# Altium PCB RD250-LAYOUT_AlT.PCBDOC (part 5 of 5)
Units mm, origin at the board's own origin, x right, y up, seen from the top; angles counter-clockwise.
Board outline 318.5 x 135 mm, 6 copper layers (TOP, Mid-Layer 1, Mid-Layer 2, Mid-Layer 3, Mid-Layer 4, BOTTOM), stack 1.422 mm thick; 550 components, 251 nets, 1350 pads, 626 vias.
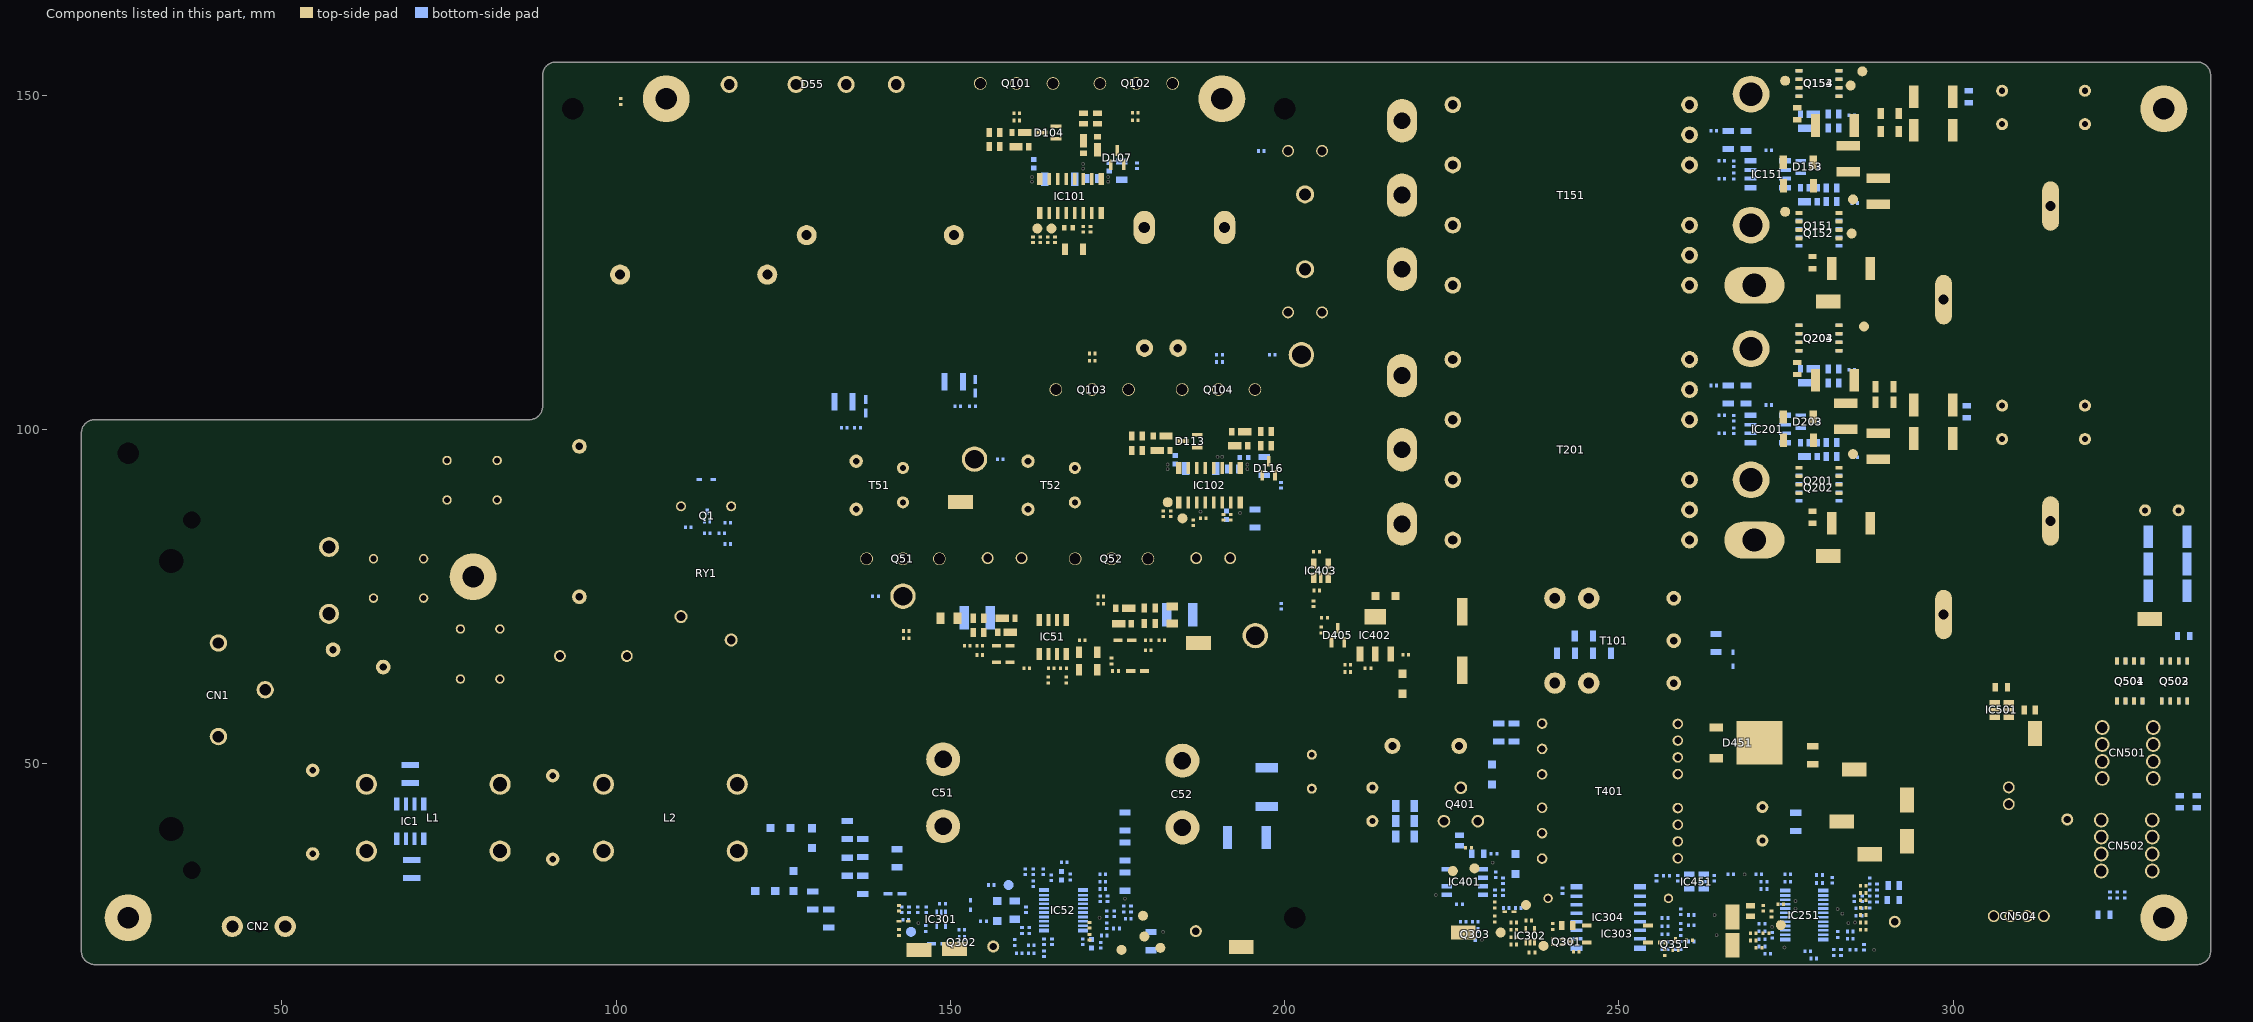
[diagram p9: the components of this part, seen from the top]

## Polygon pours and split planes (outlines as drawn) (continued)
PN on BOTTOM "BOTTOM323" (solid, pour order 144): 138.518,79.35 cw(c138.518,79.5) 138.419,79.612 138.448,79.639 cw(c138.55,79.529) 138.7,79.529 138.7,79.5 cw(c138.55,79.5) 138.55,79.35
PN on BOTTOM "BOTTOM322" (solid, pour order 143): 136.35,79.35 cw(c136.35,79.5) 136.2,79.5 136.2,79.548 cw(c136.35,79.548) 136.454,79.656 ccw(c137.46,80.7) 136.501,79.612 cw(c136.402,79.5) 136.402,79.35
LGND on BOTTOM "BOTTOM321" (solid, pour order 142): 76 vertices, not listed, extent 282.35,127.25 325.6,154.5
no net on BOTTOM "BOTTOM320" (solid, pour order 141): 17 vertices, not listed, extent 327.36,144.35 335.55,152.047
CONN003 on BOTTOM "BOTTOM319" (solid, pour order 140): 74 vertices, not listed, extent 189.15,104.9 219.95,149.4
LGND on BOTTOM "BOTTOM318" (solid, pour order 139): 48 vertices, not listed, extent 258.02,26.328 309.422,41.735
SIG00852 on BOTTOM "BOTTOM317" (solid, pour order 138): 270.7,42.25 cw(c270.7,42.4) 270.55,42.4 270.55,43.988 cw(c270.7,43.988) 270.594,44.094 270.906,44.406 cw(c271.012,44.3) 271.012,44.45 276.538,44.45 cw(c276.538,44.3) 276.644,44.406 277.306,43.744 cw(c277.2,43.638) 277.35,43.638 277.35,42.4 cw(c277.2,42.4) 277.2,42.25
SIG00343 on BOTTOM "BOTTOM316" (solid, pour order 137): 70 vertices, not listed, extent 153.65,73.05 242.16,153.1
SIG00332 on BOTTOM "BOTTOM315" (solid, pour order 136): 22 vertices, not listed, extent 257.705,61.614 268.45,67.4
CS on BOTTOM "BOTTOM314" (solid, pour order 135): 265.85,62 cw(c265.85,62.15) 265.7,62.15 265.7,65.2 cw(c265.85,65.2) 265.85,65.35 268.3,65.35 cw(c268.3,65.2) 268.45,65.2 268.45,62.15 cw(c268.3,62.15) 268.3,62
VCC12R0_2 on BOTTOM "BOTTOM313" (solid, pour order 134): 33 vertices, not listed, extent 278.25,26.376 314.522,49.25
PN on BOTTOM "BOTTOM312" (solid, pour order 133): 183.562,37.25 cw(c183.562,37.4) 183.456,37.294 181.944,38.806 cw(c182.05,38.912) 181.9,38.912 181.9,42.238 cw(c182.05,42.238) 181.944,42.344 183.606,44.006 cw(c183.712,43.9) 183.712,44.05 189.688,44.05 cw(c189.688,43.9) 189.794,44.006 192.156,41.644 cw(c192.05,41.538) 192.2,41.538 192.2,37.4 cw(c192.05,37.4) 192.05,37.25
SIG00343 on BOTTOM "BOTTOM311" (solid, pour order 132): 29 vertices, not listed, extent 177.741,111.596 201.4,118.55
PN on BOTTOM "BOTTOM310" (solid, pour order 131): 74 vertices, not listed, extent 182.7,106.072 197.949,113.7
CONN002 on BOTTOM "BOTTOM309" (solid, pour order 130): 183.4,95.75 cw(c183.4,95.9) 183.25,95.9 183.25,96.35 cw(c183.4,96.35) 183.4,96.5 187,96.5 cw(c187,96.35) 187.15,96.35 187.15,96.112 cw(c187,96.112) 187.106,96.006 186.969,95.869 cw(c186.863,95.975) 186.863,95.825 185.225,95.825 185.194,95.794 cw(c185.088,95.9) 185.088,95.75
SIG00345 on BOTTOM "BOTTOM308" (solid, pour order 129): 182.912,93.2 cw(c182.912,93.35) 182.806,93.244 182.244,93.806 cw(c182.35,93.912) 182.2,93.912 182.2,94.888 cw(c182.35,94.888) 182.244,94.994 182.431,95.181 cw(c182.537,95.075) 182.537,95.225 185.65,95.225 cw(c185.65,95.075) 185.8,95.075 185.8,93.35 cw(c185.65,93.35) 185.65,93.2
SIG00334 on BOTTOM "BOTTOM307" (solid, pour order 128): 162.162,136.3 cw(c162.162,136.45) 162.055,136.345 161.844,136.556 cw(c161.95,136.662) 161.8,136.662 161.8,139.238 cw(c161.95,139.238) 161.844,139.344 161.845,139.345 162.006,139.506 cw(c162.112,139.4) 162.112,139.55 163.138,139.55 cw(c163.138,139.4) 163.244,139.506 164.406,138.344 cw(c164.3,138.238) 164.45,138.238 164.45,136.45 cw(c164.3,136.45) 164.3,136.3
SIG00362 on BOTTOM "BOTTOM306" (solid, pour order 127): 164.762,139.75 cw(c164.762,139.9) 164.656,139.794 164.4,140.05 162.2,140.05 cw(c162.2,140.2) 162.05,140.2 162.05,141 cw(c162.2,141) 162.2,141.15 166.2,141.15 cw(c166.2,141) 166.35,141 166.35,140.212 cw(c166.2,140.212) 166.306,140.106 165.994,139.794 cw(c165.888,139.9) 165.888,139.75
SIG00354 on BOTTOM "BOTTOM305" (solid, pour order 126): 189.3,93.2 cw(c189.3,93.35) 189.15,93.35 189.15,94.9 cw(c189.3,94.9) 189.3,95.05 191.638,95.05 cw(c191.638,94.9) 191.744,95.006 191.906,94.844 cw(c191.8,94.738) 191.95,94.738 191.95,93.512 cw(c191.8,93.512) 191.906,93.406 191.744,93.244 cw(c191.638,93.35) 191.638,93.2
SIG00353 on BOTTOM "BOTTOM304" (solid, pour order 125): 39 vertices, not listed, extent 189.65,92.74 197.408,96.25
SIG00353 on BOTTOM "BOTTOM303" (solid, pour order 124): 29 vertices, not listed, extent 196.492,91.9 199.75,93.66
PN on BOTTOM "BOTTOM302" (solid, pour order 123): 194.25,93.8 cw(c194.25,93.95) 194.1,93.95 194.1,96.2 cw(c194.25,96.2) 194.25,96.35 198.7,96.35 cw(c198.7,96.2) 198.85,96.2 198.85,95.15 cw(c198.7,95.15) 198.7,95 198.162,95 cw(c198.162,95.15) 198.056,95.044 197.7,95.4 195.9,95.4 194.75,94.25 194.75,93.95 cw(c194.6,93.95) 194.6,93.8
VCC12R0_1 on BOTTOM "BOTTOM301" (solid, pour order 122): 39 vertices, not listed, extent 168.95,123.15 178.2,139.3
VCC12R0_1 on BOTTOM "BOTTOM300" (solid, pour order 121): 27 vertices, not listed, extent 199.15,71.55 204.6,91.5
LGND on BOTTOM "BOTTOM299" (solid, pour order 120): 36 vertices, not listed, extent 315,30.6 337.95,43.85
P48V on BOTTOM "BOTTOM298" (solid, pour order 119): 27 vertices, not listed, extent 315,44.85 337.95,63.7
PN on BOTTOM "BOTTOM297" (solid, pour order 118): 20 vertices, not listed, extent 173.3,136.05 176.55,139.1
SIG00336 on BOTTOM "BOTTOM296" (solid, pour order 117): 25 vertices, not listed, extent 169.55,136.9 178.2,140.65
CONN002 on BOTTOM "BOTTOM295" (solid, pour order 116): 164.66,104.85 cw(c164.66,105) 164.51,105 164.51,107.2 cw(c164.66,107.2) 164.66,107.35 166.86,107.35 cw(c166.86,107.2) 167.01,107.2 167.01,105 cw(c166.86,105) 166.86,104.85
SIG00351 on BOTTOM "BOTTOM294" (solid, pour order 115): 175.54,104.85 cw(c175.54,105) 175.39,105 175.39,107.2 cw(c175.54,107.2) 175.54,107.35 177.74,107.35 cw(c177.74,107.2) 177.89,107.2 177.89,105 cw(c177.74,105) 177.74,104.85
SIG00352 on BOTTOM "BOTTOM293" (solid, pour order 114): 194.44,104.85 cw(c194.44,105) 194.29,105 194.29,107.2 cw(c194.44,107.2) 194.44,107.35 196.64,107.35 cw(c196.64,107.2) 196.79,107.2 196.79,105 cw(c196.64,105) 196.64,104.85
CONN002 on BOTTOM "BOTTOM292" (solid, pour order 113): 189,104.85 cw(c189,105) 188.85,105 188.85,107.2 cw(c189,107.2) 189,107.35 191.2,107.35 cw(c191.2,107.2) 191.35,107.2 191.35,105 cw(c191.2,105) 191.2,104.85
PN on BOTTOM "BOTTOM291" (solid, pour order 112): 183.56,104.85 cw(c183.56,105) 183.41,105 183.41,107.2 cw(c183.56,107.2) 183.56,107.35 185.76,107.35 cw(c185.76,107.2) 185.91,107.2 185.91,105 cw(c185.76,105) 185.76,104.85
PFC_OUT on BOTTOM "BOTTOM290" (solid, pour order 111): 115.7,150.15 cw(c115.7,150.3) 115.55,150.3 115.55,153 cw(c115.7,153) 115.7,153.15 118.1,153.15 cw(c118.1,153) 118.25,153 118.25,150.3 cw(c118.1,150.3) 118.1,150.15
SIG6 on BOTTOM "BOTTOM289" (solid, pour order 110): 133.2,150.15 cw(c133.2,150.3) 133.05,150.3 133.05,153 cw(c133.2,153) 133.2,153.15 135.6,153.15 cw(c135.6,153) 135.75,153 135.75,150.3 cw(c135.6,150.3) 135.6,150.15
SIG8 on BOTTOM "BOTTOM288" (solid, pour order 109): 125.7,150.15 cw(c125.7,150.3) 125.55,150.3 125.55,153 cw(c125.7,153) 125.7,153.15 128.1,153.15 cw(c128.1,153) 128.25,153 128.25,150.3 cw(c128.1,150.3) 128.1,150.15
CONN004 on BOTTOM "BOTTOM287" (solid, pour order 108): 88 vertices, not listed, extent 298.75,64.85 337.95,149.3
FG2 on BOTTOM "BOTTOM286" (solid, pour order 107): 23 vertices, not listed, extent 323.05,22.05 335.5,31.15
SIG00440 on BOTTOM "BOTTOM285" (solid, pour order 106): 19 vertices, not listed, extent 282.35,106.25 284.6,112.05
SIG00459 on BOTTOM "BOTTOM284" (solid, pour order 105): 25 vertices, not listed, extent 264.35,100.45 275.05,107.06
SIG00429 on BOTTOM "BOTTOM283" (solid, pour order 104): 24 vertices, not listed, extent 264.35,138.55 275.05,145.16
PN on BOTTOM "BOTTOM282" (solid, pour order 103): 19 vertices, not listed, extent 190.55,84.9 198,86.95
VCC5R0_1 on BOTTOM "BOTTOM281" (solid, pour order 102): 193.012,87.3 cw(c193.012,87.45) 192.906,87.344 192.85,87.4 187.3,87.4 cw(c187.3,87.55) 187.15,87.55 187.15,88.4 cw(c187.3,88.4) 187.3,88.55 197.8,88.55 cw(c197.8,88.4) 197.95,88.4 197.95,87.45 cw(c197.8,87.45) 197.8,87.3
SIG00335 on BOTTOM "BOTTOM280" (solid, pour order 101): 168.2,136.3 cw(c168.2,136.45) 168.05,136.45 168.05,138.15 cw(c168.2,138.15) 168.2,138.3 170.65,138.3 cw(c170.65,138.15) 170.8,138.15 170.8,136.45 cw(c170.65,136.45) 170.65,136.3
LGND on BOTTOM "BOTTOM279" (solid, pour order 100): 278.65,139 cw(c278.65,139.15) 278.5,139.15 278.5,142.85 cw(c278.65,142.85) 278.65,143 281.7,143 cw(c281.7,142.85) 281.85,142.85 281.85,139.15 cw(c281.7,139.15) 281.7,139
LGND on BOTTOM "BOTTOM278" (solid, pour order 99): 278.65,100.9 cw(c278.65,101.05) 278.5,101.05 278.5,104.4 cw(c278.65,104.4) 278.65,104.55 281.7,104.55 cw(c281.7,104.4) 281.85,104.4 281.85,101.05 cw(c281.7,101.05) 281.7,100.9
SIG00342 on BOTTOM "BOTTOM277" (solid, pour order 98): 171.26,150.55 cw(c171.26,150.7) 171.11,150.7 171.11,152.9 cw(c171.26,152.9) 171.26,153.05 173.46,153.05 cw(c173.46,152.9) 173.61,152.9 173.61,150.7 cw(c173.46,150.7) 173.46,150.55
SIG115 on BOTTOM "BOTTOM276" (solid, pour order 97): 17 vertices, not listed, extent 265.95,88.6 281.2,96.1
SIG00447 on BOTTOM "BOTTOM275" (solid, pour order 96): 17 vertices, not listed, extent 265.95,126.7 281.2,134.2
SIG00450 on BOTTOM "BOTTOM274" (solid, pour order 95): 282.5,88.55 cw(c282.5,88.7) 282.35,88.7 282.35,89.55 cw(c282.5,89.55) 282.5,89.7 284.95,89.7 cw(c284.95,89.55) 285.1,89.55 285.1,88.7 cw(c284.95,88.7) 284.95,88.55
SIG00449 on BOTTOM "BOTTOM273" (solid, pour order 94): 282.5,126.65 cw(c282.5,126.8) 282.35,126.8 282.35,127.65 cw(c282.5,127.65) 282.5,127.8 284.95,127.8 cw(c284.95,127.65) 285.1,127.65 285.1,126.8 cw(c284.95,126.8) 284.95,126.65
SIG00445 on BOTTOM "BOTTOM272" (solid, pour order 93): 266.362,108.6 cw(c266.362,108.75) 266.256,108.644 265.044,109.856 cw(c265.15,109.962) 265,109.962 265,114.588 cw(c265.15,114.588) 265.044,114.694 266.706,116.356 cw(c266.812,116.25) 266.812,116.4 281.05,116.4 cw(c281.05,116.25) 281.2,116.25 281.2,111.2 cw(c281.05,111.2) 281.05,111.05 275.8,111.05 273.394,108.644 cw(c273.288,108.75) 273.288,108.6
SIG00457 on BOTTOM "BOTTOM271" (solid, pour order 92): 266.362,146.7 cw(c266.362,146.85) 266.256,146.744 265.044,147.956 cw(c265.15,148.062) 265,148.062 265,152.688 cw(c265.15,152.688) 265.044,152.794 266.706,154.456 cw(c266.812,154.35) 266.812,154.5 281.05,154.5 cw(c281.05,154.35) 281.2,154.35 281.2,149.3 cw(c281.05,149.3) 281.05,149.15 275.8,149.15 273.394,146.744 cw(c273.288,146.85) 273.288,146.7
SIG00450 on BOTTOM "BOTTOM270" (solid, pour order 91): 282.35,95.3 cw(c282.35,95.45) 282.2,95.45 282.2,98.7 cw(c282.35,98.7) 282.35,98.85 282.938,98.85 cw(c282.938,98.7) 283.044,98.806 285.006,96.844 cw(c284.9,96.738) 285.05,96.738 285.05,95.45 cw(c284.9,95.45) 284.9,95.3
VCC12R0_2 on BOTTOM "BOTTOM269" (solid, pour order 90): 262.75,104.95 cw(c262.75,105.1) 262.6,105.1 262.6,106.75 cw(c262.75,106.75) 262.75,106.9 263.8,106.9 cw(c263.8,106.75) 263.95,106.75 263.95,106.15 264.356,105.744 cw(c264.25,105.638) 264.4,105.638 264.4,105.1 cw(c264.25,105.1) 264.25,104.95
SIG00455 on BOTTOM "BOTTOM268" (solid, pour order 89): 18 vertices, not listed, extent 273.9,101.75 278.35,109.65
LGND on BOTTOM "BOTTOM267" (solid, pour order 88): 24 vertices, not listed, extent 263.79,100.45 272.2,104.36
LGND on BOTTOM "BOTTOM266" (solid, pour order 87): 266.9,100.05 cw(c266.9,100.2) 266.75,100.2 266.75,101.35 cw(c266.9,101.35) 266.9,101.5 267.988,101.5 cw(c267.988,101.35) 268.094,101.456 268.55,101 270.25,101 cw(c270.25,100.85) 270.4,100.85 270.4,100.6 cw(c270.25,100.6) 270.25,100.45 268.55,100.45 268.194,100.094 cw(c268.088,100.2) 268.088,100.05
SIG00438 on BOTTOM "BOTTOM265" (solid, pour order 86): 22 vertices, not listed, extent 274.25,95.45 278.15,100.45
SIG00456 on BOTTOM "BOTTOM264" (solid, pour order 85): 22 vertices, not listed, extent 274.25,133.55 278.15,138.55
SIG00454 on BOTTOM "BOTTOM263" (solid, pour order 84): 18 vertices, not listed, extent 273.9,139.85 278.35,147.75
LGND on BOTTOM "BOTTOM262" (solid, pour order 83): 24 vertices, not listed, extent 263.79,138.55 272.2,142.46
VCC12R0_2 on BOTTOM "BOTTOM261" (solid, pour order 82): 262.75,143.05 cw(c262.75,143.2) 262.6,143.2 262.6,144.85 cw(c262.75,144.85) 262.75,145 263.8,145 cw(c263.8,144.85) 263.95,144.85 263.95,144.25 264.356,143.844 cw(c264.25,143.738) 264.4,143.738 264.4,143.2 cw(c264.25,143.2) 264.25,143.05
LGND on BOTTOM "BOTTOM260" (solid, pour order 81): 266.9,138.15 cw(c266.9,138.3) 266.75,138.3 266.75,139.45 cw(c266.9,139.45) 266.9,139.6 267.988,139.6 cw(c267.988,139.45) 268.094,139.556 268.55,139.1 270.25,139.1 cw(c270.25,138.95) 270.4,138.95 270.4,138.7 cw(c270.25,138.7) 270.25,138.55 268.55,138.55 268.194,138.194 cw(c268.088,138.3) 268.088,138.15
PN on BOTTOM "BOTTOM259" (solid, pour order 80): 35 vertices, not listed, extent 141.15,27.576 148.8,35
PN on BOTTOM "BOTTOM258" (solid, pour order 79): 173.4,26 cw(c173.4,26.225) 173.4,26.45 174.138,26.45 174.522,26.564 cw(c174.564,26.42) 174.632,26.554 cw(c174.564,26.42) 174.71,26.383 cw(c174.565,26.42) 174.693,26.343 cw(c174.6,26.225) 174.706,26.331 cw(c174.6,26.225) 174.725,26.142 cw(c174.6,26.225) 174.698,26.111 cw(c174.565,26.18) 174.522,26.036 174.391,26.075 173.954,26.075 173.626,26.005 cw(c173.578,26.225) 173.578,26
SIG00216 on BOTTOM "BOTTOM257" (solid, pour order 78): 18 vertices, not listed, extent 163.676,33.25 165.25,33.7
SIG00524 on BOTTOM "BOTTOM256" (solid, pour order 77): 278.5,21.078 cw(c278.725,21.078) 278.505,21.126 278.575,21.454 278.575,21.6 278.494,21.681 cw(c278.6,21.787) 278.45,21.787 278.45,22.05 cw(c278.6,22.05) 278.6,22.2 278.75,22.2 cw(c278.75,22.05) 278.9,22.05 278.9,21.337 278.945,21.126 cw(c278.725,21.078) 278.95,21.078 278.95,20.9 cw(c278.725,20.9) 278.5,20.9
SIG00229 on BOTTOM "BOTTOM255" (solid, pour order 76): 17 vertices, not listed, extent 166.241,32.3 168.124,33.02
SIG00527 on BOTTOM "BOTTOM254" (solid, pour order 75): 30 vertices, not listed, extent 271.601,23.425 275.136,24.166
VREF_PSFB on BOTTOM "BOTTOM253" (solid, pour order 74): 22 vertices, not listed, extent 272.43,21.35 272.97,22.65
SIG00789 on BOTTOM "BOTTOM252" (solid, pour order 73): 27 vertices, not listed, extent 257.076,25.525 259.449,26.3
SIG00789 on BOTTOM "BOTTOM251" (solid, pour order 72): 260.088,25.975 259.804,25.975 259.476,25.905 cw(c259.428,26.125) 259.428,25.9 259.25,25.9 cw(c259.25,26.125) 259.25,26.35 259.428,26.35 cw(c259.428,26.125) 259.476,26.345 259.804,26.275 260.15,26.275 cw(c260.15,26.125) 260.256,26.231 260.257,26.23 260.481,26.006 cw(c260.375,25.9) 260.269,25.794
SIG00794 on BOTTOM "BOTTOM250" (solid, pour order 71): 31 vertices, not listed, extent 257.166,26.727 260.599,27.7
SIG00219 on BOTTOM "BOTTOM249" (solid, pour order 70): 32 vertices, not listed, extent 168.55,23.53 171.374,24.1
SIG007123 on BOTTOM "BOTTOM248" (solid, pour order 69): 40 vertices, not listed, extent 142.475,24.595 144.405,27.999
SIG007109 on BOTTOM "BOTTOM247" (solid, pour order 68): 19 vertices, not listed, extent 143.55,26.55 144.025,27.999
SIG007104 on BOTTOM "BOTTOM246" (solid, pour order 67): 19 vertices, not listed, extent 149,27.576 149.45,29.324
LGND on BOTTOM "BOTTOM245" (solid, pour order 66): 282.2,23 cw(c282.2,23.15) 282.05,23.15 282.05,24.2 cw(c282.2,24.2) 282.2,24.35 282.85,24.35 cw(c282.85,24.2) 283,24.2 283,23.15 cw(c282.85,23.15) 282.85,23
PN on BOTTOM "BOTTOM244" (solid, pour order 65): 17 vertices, not listed, extent 163.6,28.1 166.55,28.7
LGND on BOTTOM "BOTTOM243" (solid, pour order 64): 259.1,24.1 cw(c259.1,24.25) 258.95,24.25 258.95,25.35 cw(c259.1,25.35) 259.1,25.5 259.488,25.5 cw(c259.488,25.35) 259.594,25.456 259.9,25.15 260.638,25.15 cw(c260.638,25) 260.744,25.106 260.806,25.044 cw(c260.7,24.938) 260.85,24.938 260.85,24.412 cw(c260.7,24.412) 260.806,24.306 260.644,24.144 cw(c260.538,24.25) 260.538,24.1
SIG00856 on BOTTOM "BOTTOM242" (solid, pour order 63): 24 vertices, not listed, extent 228.95,33.95 231.4,37.2
SIG00863 on BOTTOM "BOTTOM241" (solid, pour order 62): 223.695,31.39 cw(c223.695,31.715) 223.651,31.393 223.648,31.393 223.157,31.465 222.55,31.465 cw(c222.55,31.715) 222.55,31.965 223.157,31.965 223.648,32.037 223.651,32.037 cw(c223.695,31.715) 223.695,32.04 224.239,32.04 cw(c224.239,31.715) 224.239,31.39
VREF_PSFB on BOTTOM "BOTTOM240" (solid, pour order 61): 17 vertices, not listed, extent 280.201,31.95 282.124,32.425
VREF_PSFB on BOTTOM "BOTTOM239" (solid, pour order 60): 280.271,31.666 280.205,31.974 cw(c280.425,32.022) 280.2,32.022 280.2,32.2 cw(c280.425,32.2) 280.65,32.2 280.65,32.022 cw(c280.425,32.022) 280.645,31.974 280.579,31.666 280.715,31.152 cw(c280.57,31.113) 280.428,31.066 cw(c280.57,31.113) 280.425,31.075 cw(c280.28,31.113) 280.422,31.066 cw(c280.28,31.113) 280.135,31.152
VREF_PSFB on BOTTOM "BOTTOM238" (solid, pour order 59): 17 vertices, not listed, extent 280.264,30.775 282.05,31.375
SIG00855 on BOTTOM "BOTTOM237" (solid, pour order 58): 21 vertices, not listed, extent 231.501,35.95 235.148,37.15
SIG00856 on BOTTOM "BOTTOM236" (solid, pour order 57): 18 vertices, not listed, extent 229.698,36.17 231.099,36.93
SIG00863 on BOTTOM "BOTTOM235" (solid, pour order 56): 225.473,37.348 224.883,37.5 224.65,37.5 cw(c224.65,37.75) 224.65,38 224.883,38 225.473,38.152 cw(c225.578,37.75) 225.578,38.165 226.15,38.165 cw(c226.15,37.75) 226.15,37.335 225.578,37.335 cw(c225.578,37.75) 225.473,37.348
LGND on BOTTOM "BOTTOM234" (solid, pour order 55): 18 vertices, not listed, extent 264.042,68.99 267.3,69.91
CSB on BOTTOM "BOTTOM233" (solid, pour order 54): 23 vertices, not listed, extent 151.837,106.78 153.974,107.8
PN on BOTTOM "BOTTOM232" (solid, pour order 53): 26 vertices, not listed, extent 196.7,140.879 200.463,142.521
CSB on BOTTOM "BOTTOM231" (solid, pour order 52): 20 vertices, not listed, extent 151.415,104.786 152.31,107.646
PN on BOTTOM "BOTTOM230" (solid, pour order 51): 199.963,141.129 ccw(c200.213,141.129) 200.463,141.129 ccw(c200.213,141.129)
SIG00864 on BOTTOM "BOTTOM229" (solid, pour order 50): 24 vertices, not listed, extent 225.75,39 229.351,41.911
SIG00847 on BOTTOM "BOTTOM228" (solid, pour order 49): 218.95,38.25 cw(c218.95,38.4) 218.8,38.4 218.8,44.5 cw(c218.95,44.5) 218.95,44.65 222.338,44.65 cw(c222.338,44.5) 222.445,44.605 224.706,42.344 cw(c224.6,42.238) 224.75,42.238 224.75,40.762 cw(c224.6,40.762) 224.706,40.656 224,39.95 224,39.062 cw(c223.85,39.062) 223.956,38.956 223.294,38.294 cw(c223.188,38.4) 223.188,38.25
PN on BOTTOM "BOTTOM227" (solid, pour order 48): 19 vertices, not listed, extent 172.275,22.25 173.714,22.82
PN on BOTTOM "BOTTOM226" (solid, pour order 47): 28 vertices, not listed, extent 163.7,20.95 171.5,23.2
PN on BOTTOM "BOTTOM225" (solid, pour order 46): 173.175,30.05 cw(c173.175,30.2) 173.025,30.2 173.025,30.425 ccw(c172.6,30.425) 173.007,30.549 cw(c173.15,30.593) 173,30.593 173,33.65 cw(c173.15,33.65) 173.15,33.8 174.2,33.8 cw(c174.2,33.65) 174.35,33.65 174.35,30.2 cw(c174.2,30.2) 174.2,30.05
SIG00843 on BOTTOM "BOTTOM224" (solid, pour order 45): 58 vertices, not listed, extent 231.326,28.226 238.81,36.16
LGND on BOTTOM "BOTTOM223" (solid, pour order 44): 25 vertices, not listed, extent 286.1,25.45 292.25,28.7
VCC12R0_1 on BOTTOM "BOTTOM222" (solid, pour order 43): 153.45,26.1 cw(c153.45,26.25) 153.3,26.25 153.3,26.7 cw(c153.45,26.7) 153.45,26.85 154.6,26.85 cw(c154.6,26.7) 154.75,26.7 154.75,26.25 cw(c154.6,26.25) 154.6,26.1
SIG0027 on BOTTOM "BOTTOM221" (solid, pour order 42): 155.3,25.9 cw(c155.3,26.05) 155.15,26.05 155.15,26.95 cw(c155.3,26.95) 155.3,27.1 157.95,27.1 158.156,27.306 cw(c158.262,27.2) 158.262,27.35 160.25,27.35 cw(c160.25,27.2) 160.4,27.2 160.4,26.4 cw(c160.25,26.4) 160.25,26.25 158.45,26.25 158.144,25.944 cw(c158.038,26.05) 158.038,25.9
SIG00523 on BOTTOM "BOTTOM220" (solid, pour order 41): 17 vertices, not listed, extent 287.276,29.1 288.824,29.6
SIG0059 on BOTTOM "BOTTOM219" (solid, pour order 40): 17 vertices, not listed, extent 287.276,30 288.824,30.5
SIG00521 on BOTTOM "BOTTOM218" (solid, pour order 39): 17 vertices, not listed, extent 287.276,30.9 288.824,31.4
SIG00520 on BOTTOM "BOTTOM217" (solid, pour order 38): 20 vertices, not listed, extent 287.276,31.8 288.9,32.3
LGND on BOTTOM "BOTTOM216" (solid, pour order 37): 22 vertices, not listed, extent 262.401,32.125 265.65,32.8
PN on BOTTOM "BOTTOM215" (solid, pour order 36): 18 vertices, not listed, extent 173.1,26.55 176.3,28.1
PFC_OFF on BOTTOM "BOTTOM214" (solid, pour order 35): 43 vertices, not listed, extent 158.85,29.525 164.174,33.699
PN on BOTTOM "BOTTOM213" (solid, pour order 34): 199.4,73.85 cw(c199.4,74) 199.25,74 199.25,74.9 cw(c199.5,74.9) 199.75,74.9 199.75,74 cw(c199.6,74) 199.6,73.85
SIGN267 on BOTTOM "BOTTOM212" (solid, pour order 33): 147.24,79.35 cw(c147.24,79.5) 147.09,79.5 147.09,81.7 cw(c147.24,81.7) 147.24,81.85 149.44,81.85 cw(c149.44,81.7) 149.59,81.7 149.59,79.5 cw(c149.44,79.5) 149.44,79.35
SIG22 on BOTTOM "BOTTOM211" (solid, pour order 32): 19 vertices, not listed, extent 141.15,79.35 144.65,90.26
SIG00819 on BOTTOM "BOTTOM210" (solid, pour order 31): 18 vertices, not listed, extent 154.196,93.965 157.2,97.235
VREF_PSFB on BOTTOM "BOTTOM209" (solid, pour order 30): 286.5,22.8 cw(c286.5,22.95) 286.35,22.95 286.35,23 285.8,23.55 284.95,23.55 cw(c284.95,23.7) 284.8,23.7 284.8,25.1 cw(c284.95,25.1) 284.95,25.25 286.038,25.25 cw(c286.038,25.1) 286.144,25.206 286.906,24.444 cw(c286.8,24.338) 286.95,24.338 286.95,22.95 cw(c286.8,22.95) 286.8,22.8
LGND on BOTTOM "BOTTOM208" (solid, pour order 29): 17 vertices, not listed, extent 279.35,20.5 283.45,22.65
SIG00446 on BOTTOM "BOTTOM207" (solid, pour order 28): 21 vertices, not listed, extent 264.55,115.8 301.45,125.15
P48V on BOTTOM "BOTTOM206" (solid, pour order 27): 321.2,26.8 cw(c321.2,26.95) 321.05,26.95 321.05,29.147 cw(c321.2,29.147) 321.2,29.297 321.9,29.297 cw(c321.9,29.147) 322.05,29.147 322.05,26.95 cw(c321.9,26.95) 321.9,26.8
SIG00356 on BOTTOM "BOTTOM205" (solid, pour order 26): 153.36,150.55 cw(c153.36,150.7) 153.21,150.7 153.21,152.9 cw(c153.36,152.9) 153.36,153.05 155.56,153.05 cw(c155.56,152.9) 155.71,152.9 155.71,150.7 cw(c155.56,150.7) 155.56,150.55
SIG00362 on BOTTOM "BOTTOM204" (solid, pour order 25): 164.24,150.55 cw(c164.24,150.7) 164.09,150.7 164.09,152.9 cw(c164.24,152.9) 164.24,153.05 166.44,153.05 cw(c166.44,152.9) 166.59,152.9 166.59,150.7 cw(c166.44,150.7) 166.44,150.55
SIG00362 on BOTTOM "BOTTOM203" (solid, pour order 24): 176.7,150.55 cw(c176.7,150.7) 176.55,150.7 176.55,152.9 cw(c176.7,152.9) 176.7,153.05 178.9,153.05 cw(c178.9,152.9) 179.05,152.9 179.05,150.7 cw(c178.9,150.7) 178.9,150.55
PN on BOTTOM "BOTTOM202" (solid, pour order 23): 182.14,150.55 cw(c182.14,150.7) 181.99,150.7 181.99,152.9 cw(c182.14,152.9) 182.14,153.05 184.34,153.05 cw(c184.34,152.9) 184.49,152.9 184.49,150.7 cw(c184.34,150.7) 184.34,150.55
SIG141 on BOTTOM "BOTTOM201" (solid, pour order 22): 328.175,64.85 cw(c328.175,65) 328.025,65 328.025,66.45 cw(c328.175,66.45) 328.175,66.6 329.975,66.6 cw(c329.975,66.45) 330.125,66.45 330.125,65 cw(c329.975,65) 329.975,64.85
SIG141 on BOTTOM "BOTTOM200" (solid, pour order 21): 334.875,64.85 cw(c334.875,65) 334.725,65 334.725,66.45 cw(c334.875,66.45) 334.875,66.6 336.675,66.6 cw(c336.675,66.45) 336.825,66.45 336.825,65 cw(c336.675,65) 336.675,64.85
SIG00512 on BOTTOM "BOTTOM199" (solid, pour order 20): 47 vertices, not listed, extent 271.05,30.125 275.037,33.724
SIG00853 on BOTTOM "BOTTOM198" (solid, pour order 19): 78 vertices, not listed, extent 203.053,32.4 239.499,57.6
SIG00448 on BOTTOM "BOTTOM197" (solid, pour order 18): 20 vertices, not listed, extent 264.55,68.65 300.15,87.05
SIG00439 on BOTTOM "BOTTOM196" (solid, pour order 17): 19 vertices, not listed, extent 282.35,144.35 284.6,150.15
P48V on BOTTOM "BOTTOM195" (solid, pour order 16): 307.3,45.5 cw(c307.3,45.65) 307.15,45.65 307.15,47.35 cw(c307.3,47.35) 307.3,47.5 309.3,47.5 cw(c309.3,47.35) 309.45,47.35 309.45,45.65 cw(c309.3,45.65) 309.3,45.5
LGND on BOTTOM "BOTTOM194" (solid, pour order 15): 307.3,43 cw(c307.3,43.15) 307.15,43.15 307.15,44.85 cw(c307.3,44.85) 307.3,45 309.3,45 cw(c309.3,44.85) 309.45,44.85 309.45,43.15 cw(c309.3,43.15) 309.3,43
LGND on BOTTOM "BOTTOM193" (solid, pour order 14): 335.1,68.45 cw(c335.1,68.6) 334.95,68.6 334.95,71.45 332.794,73.606 cw(c332.9,73.712) 332.75,73.712 332.75,88.488 cw(c332.9,88.488) 332.794,88.594 333.656,89.456 cw(c333.762,89.35) 333.762,89.5 337.85,89.5 cw(c337.85,89.35) 338,89.35 338,68.6 cw(c337.85,68.6) 337.85,68.45
SIG00449 on BOTTOM "BOTTOM192" (solid, pour order 13): 282.35,133.4 cw(c282.35,133.55) 282.2,133.55 282.2,136.8 cw(c282.35,136.8) 282.35,136.95 282.938,136.95 cw(c282.938,136.8) 283.044,136.906 285.006,134.944 cw(c284.9,134.838) 285.05,134.838 285.05,133.55 cw(c284.9,133.55) 284.9,133.4
SIG00842 on BOTTOM "BOTTOM191" (solid, pour order 12): 18 vertices, not listed, extent 224.8,49.3 235.15,53.8
LGND on BOTTOM "BOTTOM190" (solid, pour order 11): 269.5,22.4 cw(c269.5,22.55) 269.35,22.55 269.35,26.25 cw(c269.5,26.25) 269.5,26.4 271.05,26.4 cw(c271.05,26.25) 271.2,26.25 271.2,22.55 cw(c271.05,22.55) 271.05,22.4
SIG00526 on BOTTOM "BOTTOM189" (solid, pour order 10): 271.75,24.6 cw(c271.75,24.75) 271.6,24.75 271.6,26.25 cw(c271.75,26.25) 271.75,26.4 272.588,26.4 cw(c272.588,26.25) 272.694,26.356 273.725,25.325 274.837,25.325 cw(c274.837,25.125) 274.837,24.925 273.725,24.925 273.444,24.644 cw(c273.338,24.75) 273.338,24.6
VCC12R0_2 on BOTTOM "BOTTOM188" (solid, pour order 9): 19 vertices, not listed, extent 266.9,33.106 270.7,33.9
LGND on BOTTOM "BOTTOM187" (solid, pour order 8): 272.162,30.8 cw(c272.162,30.95) 272.056,30.844 271.944,30.956 cw(c272.05,31.062) 271.9,31.062 271.9,33.438 cw(c272.05,33.438) 271.944,33.544 272.156,33.756 cw(c272.262,33.65) 272.262,33.8 274.9,33.8 cw(c274.9,33.65) 275.05,33.65 275.05,31.85 275.556,31.344 cw(c275.45,31.238) 275.6,31.238 275.6,30.95 cw(c275.45,30.95) 275.45,30.8
PN on BOTTOM "BOTTOM186" (solid, pour order 7): 19 vertices, not listed, extent 212.05,38.25 217.2,44.65
PN on BOTTOM "BOTTOM185" (solid, pour order 6): 241,29.4 cw(c241,29.55) 240.85,29.55 240.85,30.7 cw(c241,30.7) 241,30.85 241.888,30.85 cw(c241.888,30.7) 241.994,30.806 242.3,30.5 244.2,30.5 cw(c244.2,30.35) 244.35,30.35 244.35,30.1 cw(c244.2,30.1) 244.2,29.95 242.15,29.95 241.644,29.444 cw(c241.538,29.55) 241.538,29.4
SIG00841 on BOTTOM "BOTTOM184" (solid, pour order 5): 226.35,45.45 cw(c226.35,46.45) 226.35,47.45 cw(c226.662,46.5) 226.662,47.5 234.736,47.5 236.393,49.157 cw(c237.1,48.45) 237.1,49.45 238.5,49.45 cw(c238.5,48.45) 238.5,47.45 237.514,47.45 235.807,45.743 cw(c235.1,46.45) 235.1,45.45
PN on BOTTOM "BOTTOM183" (solid, pour order 4): 18 vertices, not listed, extent 160.9,33.55 167.05,35.6
PN on BOTTOM "BOTTOM182" (solid, pour order 3): 19 vertices, not listed, extent 159.3,21.4 161.9,23.2
PN on BOTTOM "BOTTOM181" (solid, pour order 2): 154.812,28.9 cw(c154.812,29.05) 154.706,28.944 154.444,29.206 cw(c154.55,29.312) 154.4,29.312 154.4,29.788 cw(c154.55,29.788) 154.444,29.894 154.606,30.056 cw(c154.712,29.95) 154.712,30.1 160.25,30.1 cw(c160.25,29.95) 160.4,29.95 160.4,29.05 cw(c160.25,29.05) 160.25,28.9
no net on Top Solder "TOPSOLDER373" (solid, pour order 0): 161.75,133.95 cw(c161.75,134.95) 161.75,135.95 174.25,135.95 cw(c174.25,134.95) 174.25,133.95
no net on Top Solder "TOPSOLDER372" (solid, pour order 0): 182.55,90.7 cw(c182.55,91.7) 182.55,92.7 195.05,92.7 cw(c195.05,91.7) 195.05,90.7
no net on Bottom Solder "BOTTOMSOLDER375" (solid, pour order 0): 161.75,133.95 cw(c161.75,134.95) 161.75,135.95 174.25,135.95 cw(c174.25,134.95) 174.25,133.95
no net on Bottom Solder "BOTTOMSOLDER374" (solid, pour order 0): 182.55,90.7 cw(c182.55,91.7) 182.55,92.7 195.05,92.7 cw(c195.05,91.7) 195.05,90.7

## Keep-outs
Keep-Out Layer:
  lines w0.1: 20,22 ccw(c22,22) 22,20 ; 20,22 ccw(c22,22) 22,20 ; 20,22 20,99.5 ; 20,22 20,99.5 ; 20,99.5 cw(c22,99.5) 22,101.5 ; 20,99.5 cw(c22,99.5) 22,101.5 ; 22,20 206.311,20 ; 22,20 206.311,20 ; 22,101.5 87,101.5 ; 22,101.5 87,101.5 ; 87,101.5 ccw(c87,103.5) 89,103.5 ; 87,101.5 ccw(c87,103.5) 89,103.5 ; 89,103.5 89,153 ; 89,103.5 89,153 ; 89,153 cw(c91,153) 91,155 ; 89,153 cw(c91,153) 91,155 ; 91,155 336.5,155 ; 91,155 336.5,155 ; 206.311,20 336.5,20 ; 206.311,20 336.5,20 ; 336.5,20 ccw(c336.5,22) 338.5,22 ; 336.5,20 ccw(c336.5,22) 338.5,22 ; 336.5,155 cw(c336.5,153) 338.5,153 ; 336.5,155 cw(c336.5,153) 338.5,153 ; 338.5,22 338.5,153 ; 338.5,22 338.5,153

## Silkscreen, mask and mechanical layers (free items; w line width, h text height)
Top Overlay:
  drawing of 186 lines, arcs and shapes, not listed
  text "BK-F" at 212.7,145.08 h0.43 r90
  text "TU-F" at 213.7,145.08 h0.43 r90
  text "CK-S" at 268.83,143.7 h0.43
  text "BK-F" at 268.58,136.3 h0.43
  text "BK-S" at 212.7,134.08 h0.43 r90
  text "CL-F" at 213.7,134.08 h0.43 r90
  text "TU-S" at 212.7,123.08 h0.43 r90
  text "CL-S" at 213.7,123.08 h0.43 r90
  text "BK-S" at 276.08,118.05 h0.43
  text "CL-F" at 276.08,117.05 h0.43
  text "BK-F" at 212.7,107.03 h0.43 r90
  text "TU-F" at 213.7,107.03 h0.43 r90
  text "CK-S" at 268.78,105.25 h0.43
  text "BK-F" at 268.88,98.3 h0.43
  text "BK-S" at 212.7,95.93 h0.43 r90
  text "CL-F" at 213.7,95.93 h0.43 r90
  text "CAUTION" at 43.015,93 h2.24
  text "FOR CONTINUED PROTECTION AGAINST RISK OF FIRE." at 29.84,91.26 h0.8
  text "OUTC1" at 175.315,90.2 h0.43
  text "REPLACE ONLY WITH SAME TYPE" at 45.89,89.08 h1
  text "OUTD1" at 177.915,85.65 h0.43
  text "TU-S" at 212.7,84.83 h0.43 r90
  text "CL-S" at 213.7,84.83 h0.43 r90
  text "BK-S" at 269.08,76.55 h0.43
  text "CL-F" at 269.08,75.55 h0.43
  text "250V T15AH" at 52.27,73.085 h1 r90
  text "RD250" at 277.715,69.85 h0.43
  text "SAA007601010" at 275.56,68.7 h0.43
  text "SGB007601000" at 275.61,67.45 h0.43
Bottom Overlay:
  drawing of 231 lines, arcs and shapes, not listed
  text "A" at 154.225,21.15 h0.43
